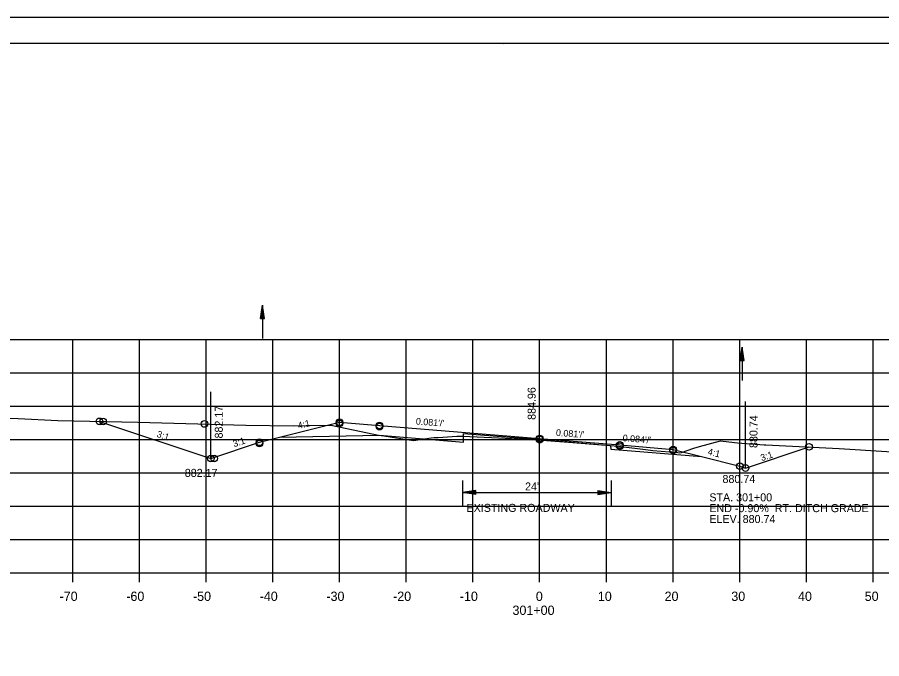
# Model space of a CAD drawing. Extents: x 1486524 to 1499135, y 326561 to 337924.
# Drawn here: x 1488904.6 to 1489034.2, y 333963.1 to 334059.3 of the extents above; entities that cross this region are included whole.
import ezdxf

# ---------------------------------------------------------------- set-up
doc = ezdxf.new("R2010")
doc.units = 0
for name, color, linetype in [('E_Const Align', 7, 'Continuous'), ('E_Const Align Station', 7, 'Continuous'), ('E_Ownership Information', 7, 'Continuous'), ('E_Property Line', 7, 'Continuous'), ('E_Proposed ROW and Easements', 7, 'Continuous'), ('E_Proposed ROW Fig Annot', 7, 'Continuous'), ('E_Quarter Calls', 7, 'Continuous'), ('E_Survey Point', 7, 'Continuous'), ('E_Title Sheet', 7, 'Continuous'), ('E_Tract Number', 7, 'Continuous'), ('R_Water Annot', 7, 'Continuous'), ('R_Xsect Elev', 7, 'Continuous'), ('R_Xsect Slope', 7, 'Continuous')]:
    doc.layers.add(name, color=color, linetype=linetype)

msp = doc.modelspace()

# ---------------------------------------------------------------- linework, layer by layer
at = {"layer": 'E_Const Align'}
for p, q in [((1488842.89, 333975.98), (1489122.89, 333975.98)), ((1488912.89, 333974.58), (1488912.89, 333975.98)), ((1488922.89, 333974.58), (1488922.89, 333975.98)), ((1488932.89, 333974.58), (1488932.89, 333975.98)), ((1488942.89, 333974.58), (1488942.89, 333975.98)), ((1488952.89, 333974.58), (1488952.89, 333975.98)), ((1488962.89, 333974.58), (1488962.89, 333975.98)), ((1488972.89, 333974.58), (1488972.89, 333975.98)), ((1488982.89, 333974.58), (1488982.89, 333975.98)), ((1488992.89, 333974.58), (1488992.89, 333975.98)), ((1489002.89, 333974.58), (1489002.89, 333975.98)), ((1489012.89, 333974.58), (1489012.89, 333975.98)), ((1489022.89, 333974.58), (1489022.89, 333975.98)), ((1489032.89, 333974.58), (1489032.89, 333975.98))]:
    msp.add_line(p, q, dxfattribs=at)
at = {"layer": 'E_Ownership Information'}
for p, q in [((1488842.89, 334010.98), (1489122.89, 334010.98)), ((1488912.89, 333975.98), (1488912.89, 334010.98)), ((1488922.89, 333975.98), (1488922.89, 334010.98)), ((1488932.89, 333975.98), (1488932.89, 334010.98)), ((1488942.89, 333975.98), (1488942.89, 334010.98)), ((1488952.89, 333975.98), (1488952.89, 334010.98)), ((1488962.89, 333975.98), (1488962.89, 334010.98)), ((1488972.89, 333975.98), (1488972.89, 334010.98)), ((1488982.89, 333975.98), (1488982.89, 334010.98)), ((1488992.89, 333975.98), (1488992.89, 334010.98)), ((1489002.89, 333975.98), (1489002.89, 334010.98)), ((1489012.89, 333975.98), (1489012.89, 334010.98)), ((1489022.89, 333975.98), (1489022.89, 334010.98)), ((1489032.89, 333975.98), (1489032.89, 334010.98)), ((1488842.89, 334005.98), (1489122.89, 334005.98)), ((1488842.89, 334000.98), (1489122.89, 334000.98)), ((1488842.89, 333995.98), (1489122.89, 333995.98)), ((1488842.89, 333990.98), (1489122.89, 333990.98)), ((1488842.89, 333985.98), (1489122.89, 333985.98)), ((1488842.89, 333980.98), (1489122.89, 333980.98)), ((1488842.89, 333975.98), (1489122.89, 333975.98))]:
    msp.add_line(p, q, dxfattribs=at)
at = {"layer": 'E_Property Line'}
for p, q in [((1488824.89, 334055.44), (1489141.07, 334055.44)), ((1488977.41, 334055.18), (1488977.41, 334055.18)), ((1488977.41, 334055.18), (1488977.41, 334055.18))]:
    msp.add_line(p, q, dxfattribs=at)
at = {"layer": 'E_Proposed ROW and Easements'}
for p, q in [((1488971.31, 333989.86), (1488971.31, 333985.93)), ((1488993.59, 333989.86), (1488993.59, 333985.93)), ((1488973.31, 333988.34), (1488971.31, 333988.04)), ((1488973.31, 333987.74), (1488971.31, 333988.04)), ((1488973.31, 333988.29), (1488971.65, 333988.04)), ((1488973.31, 333987.79), (1488971.65, 333988.04)), ((1488973.31, 333988.24), (1488971.99, 333988.04)), ((1488973.31, 333987.84), (1488971.99, 333988.04)), ((1488973.31, 333988.19), (1488972.32, 333988.04)), ((1488973.31, 333987.89), (1488972.32, 333988.04)), ((1488973.31, 333988.14), (1488972.66, 333988.04)), ((1488973.31, 333987.94), (1488972.66, 333988.04)), ((1488973.31, 333988.09), (1488973, 333988.04)), ((1488973.31, 333987.99), (1488973, 333988.04)), ((1488973.31, 333987.74), (1488973.31, 333988.34)), ((1488991.59, 333988.34), (1488993.59, 333988.04)), ((1488991.59, 333988.34), (1488991.59, 333987.74)), ((1488991.59, 333988.29), (1488993.26, 333988.04)), ((1488991.59, 333988.24), (1488992.91, 333988.04)), ((1488991.59, 333988.19), (1488992.58, 333988.04)), ((1488991.59, 333988.14), (1488992.24, 333988.04)), ((1488991.59, 333988.09), (1488991.91, 333988.04)), ((1488991.59, 333987.74), (1488993.59, 333988.04)), ((1488991.59, 333987.95), (1488992.24, 333988.04)), ((1488991.59, 333987.84), (1488992.91, 333988.04)), ((1488991.59, 333987.79), (1488993.26, 333988.04)), ((1488991.59, 333987.89), (1488992.58, 333988.04)), ((1488991.59, 333988), (1488991.91, 333988.04))]:
    msp.add_line(p, q, dxfattribs=at)
at = {"layer": 'E_Proposed ROW Fig Annot'}
for p, q in [((1488941.03, 334014.17), (1488941.33, 334016.17)), ((1488941.08, 334014.17), (1488941.33, 334015.84)), ((1488941.63, 334014.17), (1488941.33, 334016.17)), ((1488941.58, 334014.17), (1488941.33, 334015.84)), ((1488941.13, 334014.17), (1488941.33, 334015.49)), ((1488941.18, 334014.17), (1488941.33, 334015.16)), ((1488941.24, 334014.17), (1488941.33, 334014.82)), ((1488941.29, 334014.17), (1488941.33, 334014.49)), ((1488941.53, 334014.17), (1488941.33, 334015.49)), ((1488941.48, 334014.17), (1488941.33, 334015.16)), ((1488941.43, 334014.17), (1488941.33, 334014.82)), ((1488941.38, 334014.17), (1488941.33, 334014.49)), ((1488941.03, 334014.17), (1488941.63, 334014.17)), ((1489012.94, 334007.85), (1489013.24, 334009.85)), ((1489012.99, 334007.85), (1489013.24, 334009.52)), ((1489013.54, 334007.85), (1489013.24, 334009.85)), ((1489013.49, 334007.85), (1489013.24, 334009.52)), ((1489013.04, 334007.85), (1489013.24, 334009.17)), ((1489013.09, 334007.85), (1489013.24, 334008.84)), ((1489013.14, 334007.85), (1489013.24, 334008.5)), ((1489013.19, 334007.85), (1489013.24, 334008.17)), ((1489013.44, 334007.85), (1489013.24, 334009.17)), ((1489013.39, 334007.85), (1489013.24, 334008.84)), ((1489013.34, 334007.85), (1489013.24, 334008.5)), ((1489013.29, 334007.85), (1489013.24, 334008.17)), ((1489012.94, 334007.85), (1489013.54, 334007.85)), ((1488971.31, 333988.04), (1488993.59, 333988.04))]:
    msp.add_line(p, q, dxfattribs=at)
at = {"layer": 'E_Quarter Calls'}
msp.add_line((1488812.48, 334059.33), (1489145.82, 334059.33), dxfattribs=at)
for points in [[(1488812.48, 334059.33), (1489145.82, 334059.33), (1489145.82, 333846), (1488812.48, 333846)], [(1489058.81, 334055.44), (1489058.81, 334045.56), (1489094.54, 334045.56), (1489094.54, 334042.64), (1489117.74, 334042.64), (1489117.74, 334018.31), (1489141.07, 334018.31), (1489141.07, 333849.98), (1488824.89, 333849.98), (1488824.89, 334055.44)]]:
    msp.add_lwpolyline(points, close=True, dxfattribs=at)
for centre in [(1488916.9, 333998.72), (1488917.45, 333998.7), (1488952.89, 333998.58), (1488952.89, 333998.58), (1488952.89, 333998.41), (1488932.64, 333998.33), (1488958.89, 333998.1), (1488958.89, 333998.1), (1488958.89, 333997.93), (1488982.89, 333996.15), (1488982.89, 333996.15), (1488982.89, 333995.98), (1488940.89, 333995.58), (1488940.89, 333995.58), (1488940.89, 333995.41), (1488994.89, 333995.18), (1488994.89, 333995.18), (1488994.89, 333995.01), (1489002.89, 333994.51), (1489002.89, 333994.51), (1489023.27, 333994.89), (1489002.89, 333994.34), (1488933.59, 333993.15), (1488934.1, 333993.15), (1489012.89, 333992.01), (1489012.89, 333992.01), (1489013.75, 333991.72), (1489013.75, 333991.72)]:
    msp.add_circle(centre, 0.5, dxfattribs=at)
at = {"layer": 'E_Survey Point'}
msp.add_lwpolyline([(1488943.9, 333996.34), (1488958.89, 333996.64), (1488971.49, 333995.62), (1488971.49, 333996.91), (1488982.89, 333995.99), (1488993.53, 333995.12), (1488993.54, 333994.54), (1489007.17, 333993.44)], dxfattribs=at)
at = {"layer": 'E_Title Sheet'}
msp.add_lwpolyline([(1488916.9, 333998.72), (1488933.59, 333993.15), (1488940.89, 333995.58), (1488943.9, 333996.34), (1488952.89, 333998.58), (1488958.89, 333998.1), (1488982.89, 333996.15), (1488994.89, 333995.18), (1489002.89, 333994.51), (1489007.17, 333993.44), (1489012.89, 333992.01), (1489013.75, 333991.72), (1489023.27, 333994.89)], dxfattribs=at)
at = {"layer": 'E_Tract Number'}
msp.add_lwpolyline([(1488879.35, 334000.16), (1488904.71, 333999.14), (1488910.64, 333998.85), (1488922.65, 333998.59), (1488938.85, 333998.17), (1488945.98, 333998.05), (1488947.88, 333998.1), (1488951.59, 333998.17), (1488956.14, 333997.2), (1488958.74, 333996.63), (1488959.51, 333996.55), (1488963.96, 333995.87), (1488966.61, 333996.25), (1488967.07, 333996.28), (1488967.69, 333996.31), (1488970.49, 333996.49), (1488970.99, 333996.49), (1488971.36, 333996.48), (1488976.73, 333996.23), (1488982.56, 333995.96), (1488987.86, 333995.53), (1488993.41, 333995.12), (1488994.08, 333995.06), (1488994.69, 333995), (1488999.16, 333994.44), (1488999.84, 333994.35), (1489003.59, 333994.04), (1489003.88, 333994), (1489004.14, 333994.06), (1489006.01, 333994.71), (1489006.83, 333994.95), (1489009.98, 333995.82), (1489011.27, 333995.67), (1489012.54, 333995.51), (1489016.53, 333995.2), (1489016.63, 333995.19), (1489016.8, 333995.19), (1489027.81, 333994.67), (1489041.29, 333993.79)], dxfattribs=at)
at = {"layer": 'R_Water Annot'}
for p, q in [((1488941.33, 334016.17), (1488941.33, 334011.17)), ((1489013.24, 334009.85), (1489013.24, 334004.85))]:
    msp.add_line(p, q, dxfattribs=at)
at = {"layer": 'R_Xsect Elev'}
for p, q in [((1488982.89, 333995.94), (1488982.89, 334005.94)), ((1488933.59, 333993.15), (1488933.59, 334003.15)), ((1489013.75, 333991.72), (1489013.75, 334001.72))]:
    msp.add_line(p, q, dxfattribs=at)

# ---------------------------------------------------------------- texts
at = {"layer": 'E_Const Align Station'}
for s, p in [('-70', (1488910.92, 333971.78)), ('-60', (1488920.92, 333971.78)), ('-50', (1488930.92, 333971.78)), ('-40', (1488940.92, 333971.78)), ('-30', (1488950.92, 333971.78)), ('-20', (1488960.92, 333971.78)), ('-10', (1488970.92, 333971.78)), ('0', (1488982.32, 333971.78)), ('10', (1488991.62, 333971.78)), ('20', (1489001.62, 333971.78)), ('30', (1489011.62, 333971.78)), ('40', (1489021.62, 333971.78)), ('50', (1489031.62, 333971.78)), ('301+00', (1488978.82, 333969.68))]:
    msp.add_text(s, height=1.4, dxfattribs=at).set_placement(p)
at = {"layer": 'E_Proposed ROW Fig Annot'}
for s, p in [("24'", (1488980.7, 333988.35)), ('STA. 301+00 ', (1489008.33, 333986.72)), ('EXISTING ROADWAY', (1488971.93, 333985.14)), ('END -0.90%  RT. DITCH GRADE', (1489008.33, 333985.1)), ('ELEV. 880.74', (1489008.33, 333983.47))]:
    msp.add_text(s, height=1.2, dxfattribs=at).set_placement(p)
at = {"layer": 'R_Xsect Elev'}
for s, rotation, p in [('884.96', 90, (1488982.29, 333998.94)), ('882.17', 90, (1488935.39, 333996.15)), ('880.74', 90, (1489015.55, 333994.72)), ('880.74', 360, (1489010.3, 333989.48))]:
    msp.add_text(s, height=1.2, rotation=rotation, dxfattribs=at).set_placement(p)
msp.add_text('882.17', height=1.2, dxfattribs=at).set_placement((1488929.69, 333990.39))
at = {"layer": 'R_Xsect Slope'}
for s, rotation, p in [('4:1', 14.0362, (1488946.76, 333997.57)), ("0.081'/'", 355.3689, (1488964.3, 333998.26)), ('3:1', 341.5651, (1488925.41, 333996.41)), ('3:1', 18.4349, (1488937.08, 333994.84)), ("0.081'/'", 355.3689, (1488985.3, 333996.56)), ("0.084'/'", 355.188, (1488995.3, 333995.75)), ('4:1', 345.9638, (1489008.01, 333993.74)), ('3:1', 18.4349, (1489016.19, 333992.74))]:
    msp.add_text(s, height=1, rotation=rotation, dxfattribs=at).set_placement(p)

doc.saveas('drawing.dxf')
